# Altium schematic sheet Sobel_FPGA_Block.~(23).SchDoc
size A2
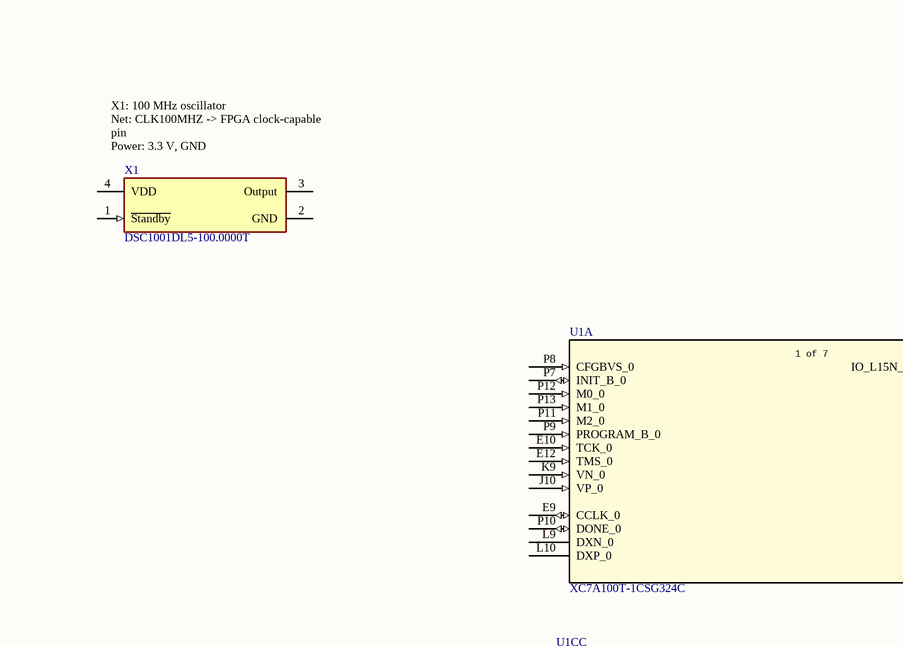
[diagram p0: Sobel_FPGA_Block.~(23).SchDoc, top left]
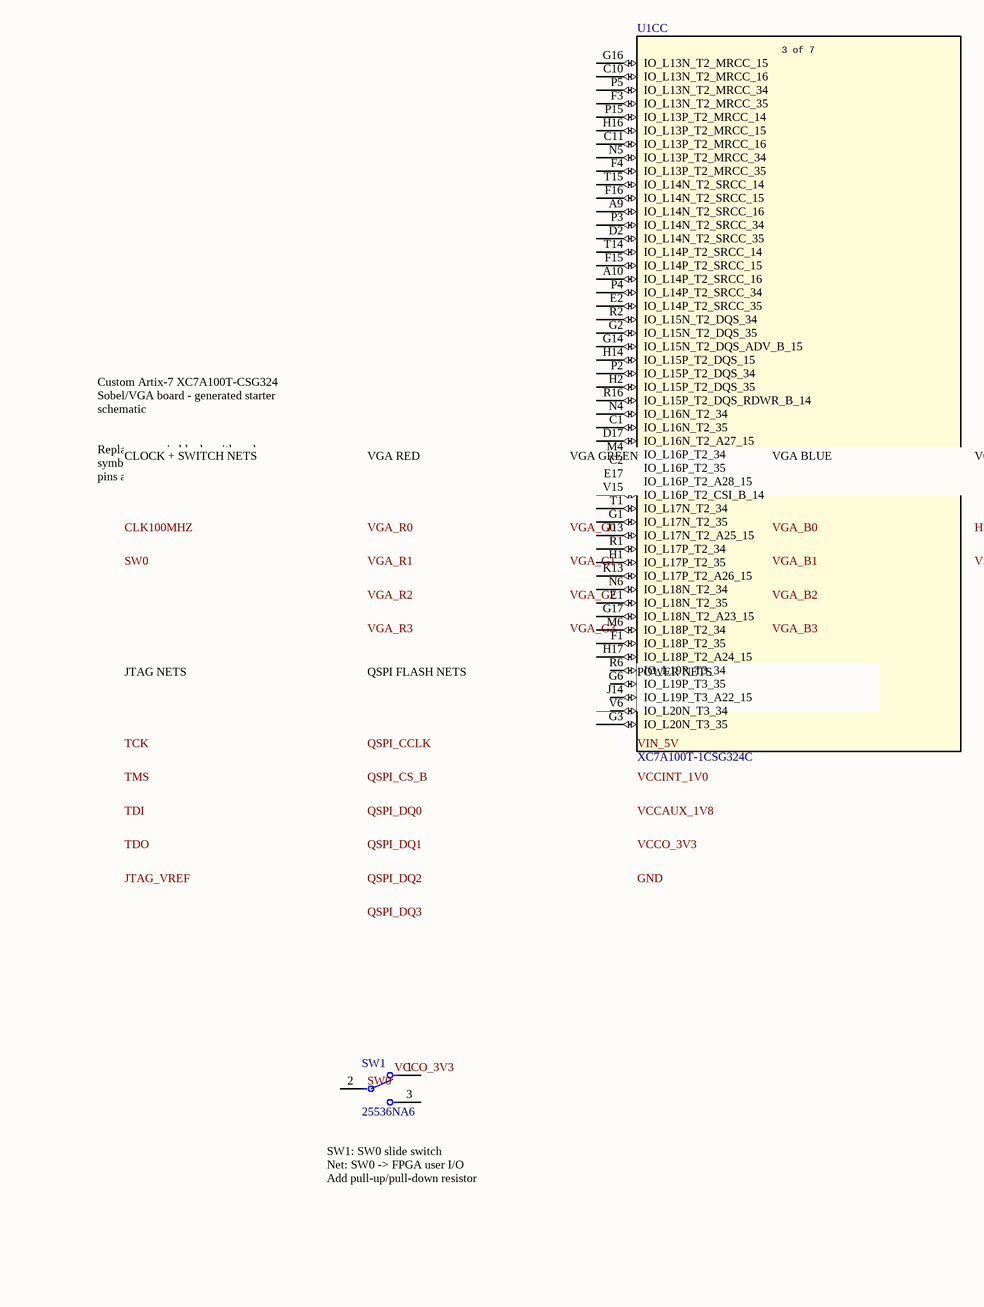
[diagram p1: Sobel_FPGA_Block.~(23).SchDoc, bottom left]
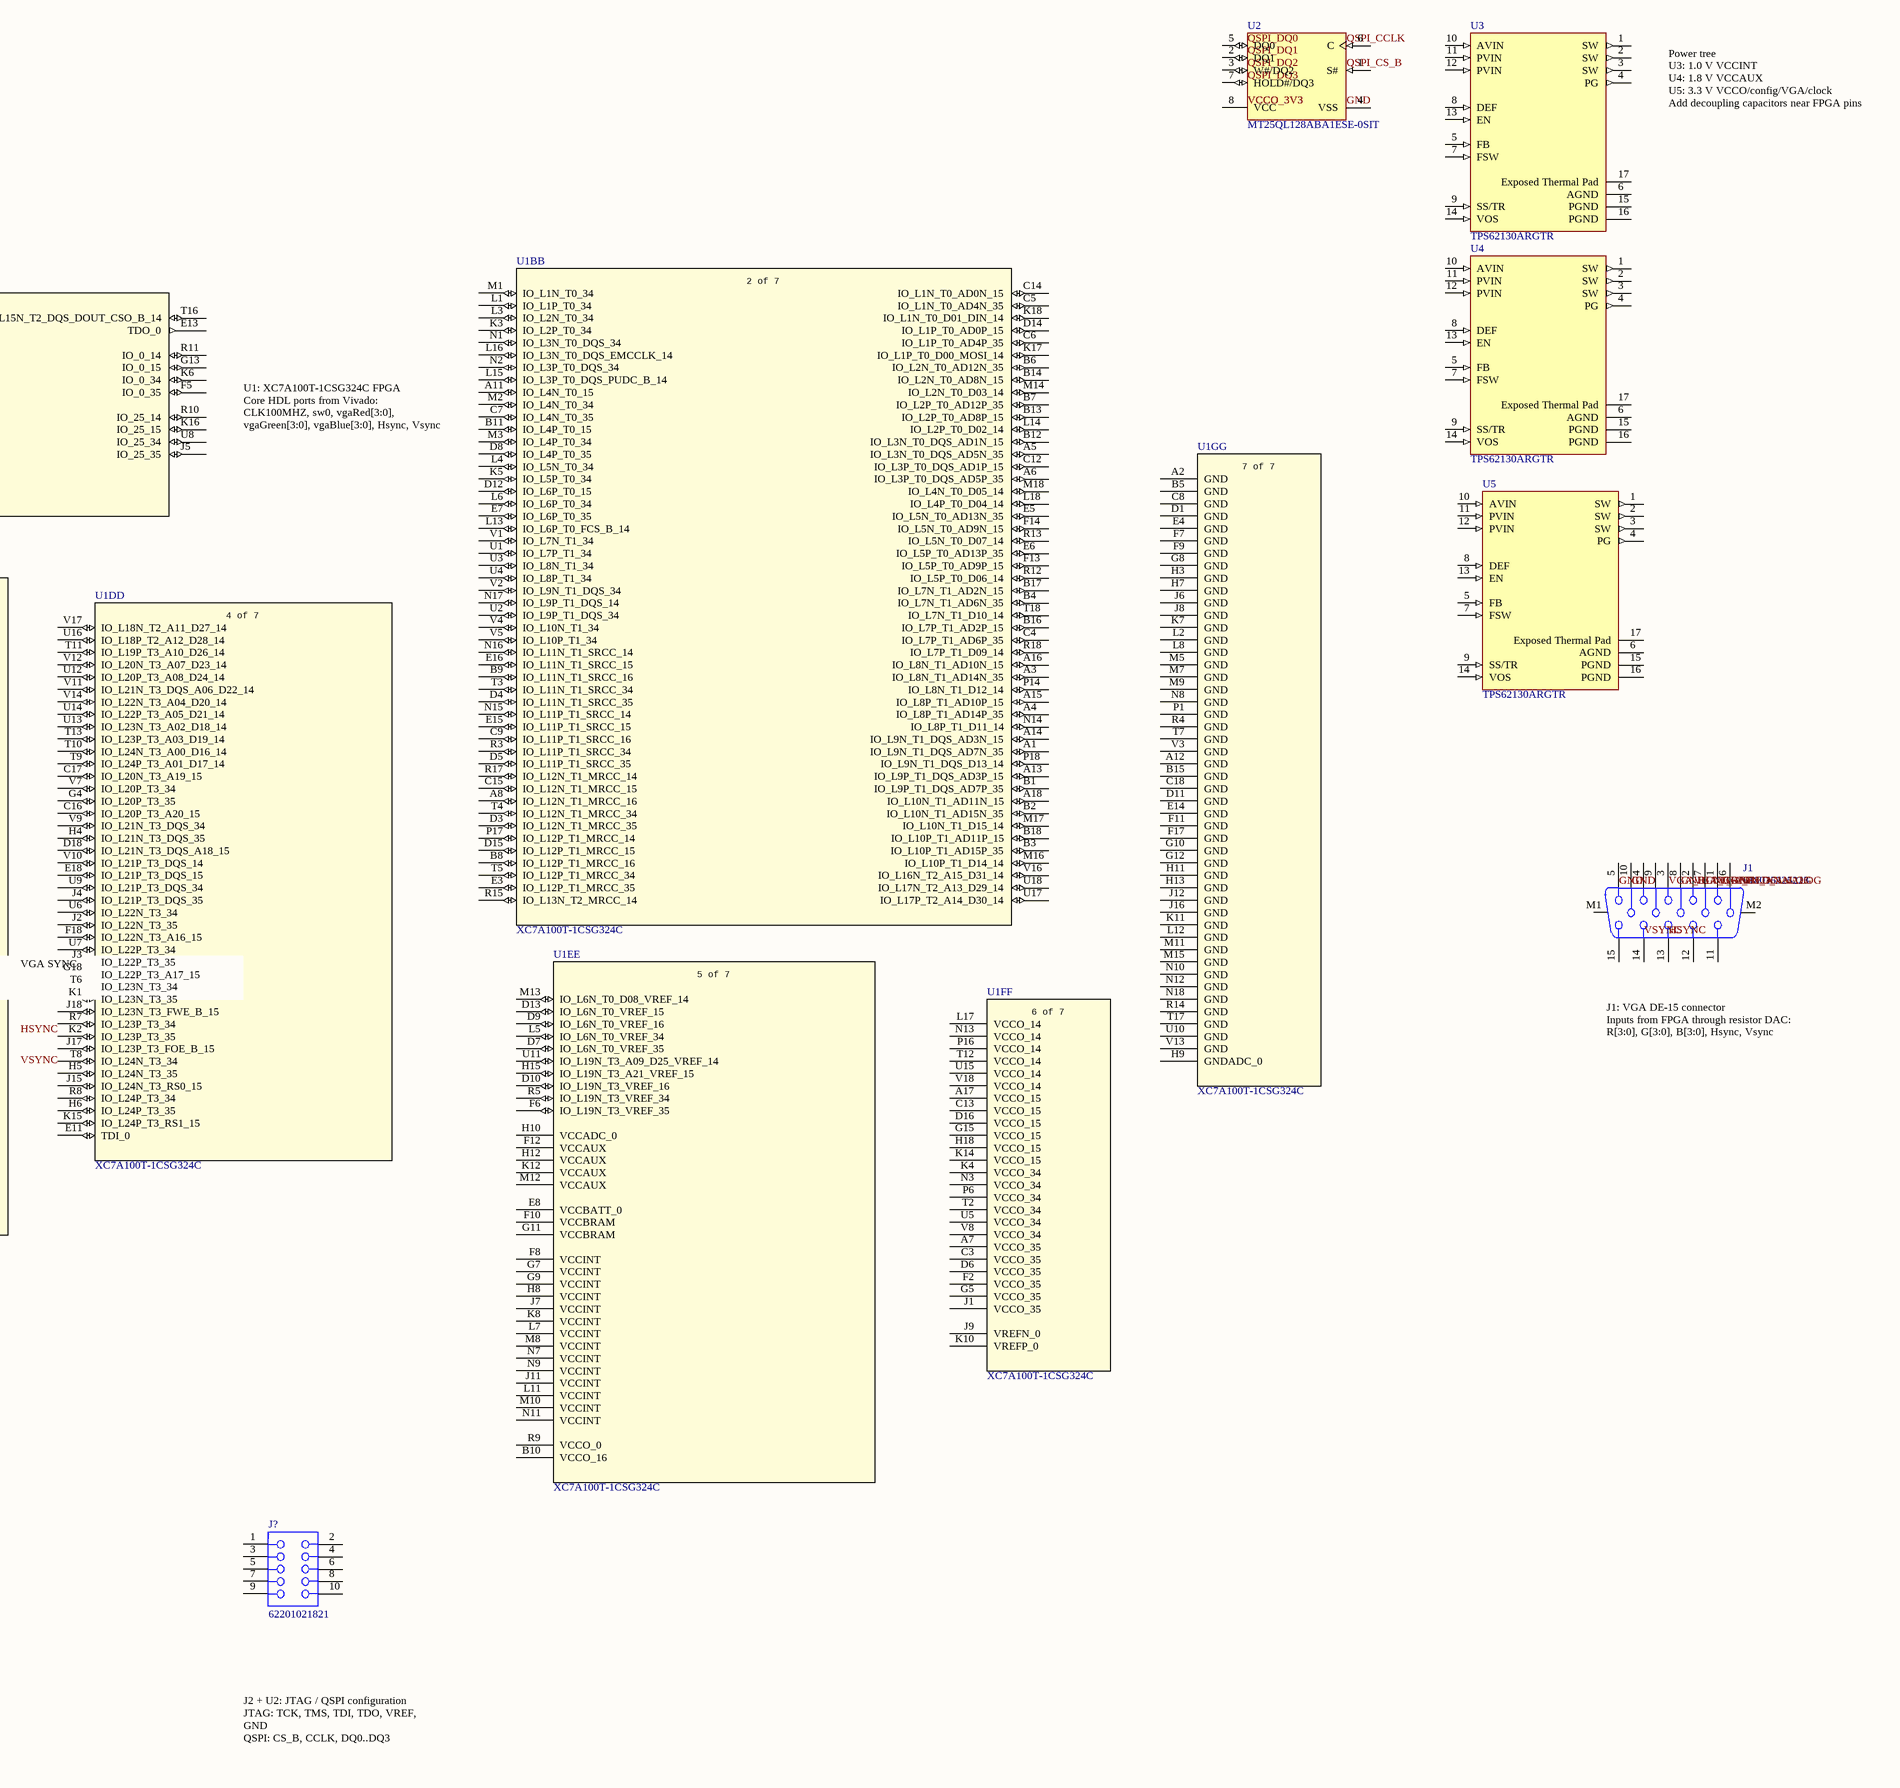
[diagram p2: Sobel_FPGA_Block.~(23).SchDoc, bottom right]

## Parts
J1  618015325223  [618015325223]
J?  62201021821  [62201021821]
SW1  25536NA6  [FP-25536NA6-0]
U1  XC7A100T-1CSG324C  [CSG324_XIL]  (part A of 7)
U1B  XC7A100T-1CSG324C  [CSG324_XIL]  (part B of 7)
U1C  XC7A100T-1CSG324C  [CSG324_XIL]  (part C of 7)
U1D  XC7A100T-1CSG324C  [CSG324_XIL]  (part D of 7)
U1E  XC7A100T-1CSG324C  [CSG324_XIL]  (part E of 7)
U1F  XC7A100T-1CSG324C  [CSG324_XIL]  (part F of 7)
U1G  XC7A100T-1CSG324C  [CSG324_XIL]  (part G of 7)
U2  MT25QL128ABA1ESE-0SIT  [MICT-SE-8_M]
U3  TPS62130ARGTR  [FP-RGT0016C-IPC_C]
U4  TPS62130ARGTR  [FP-RGT0016C-IPC_C]
U5  TPS62130ARGTR  [FP-RGT0016C-IPC_C]
X1  DSC1001DL5-100.0000T  [FP-CDFN2520-4LD-PL-1-MFG]

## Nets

Not connected (* = marked no-connect by the designer): J1 1 2 3 4 5 6 7 8 9 10 11 12 13 14 15 M1 M2; J? 1 2 3 4 5 6 7 8 9 10; SW1 1 2 3; U1 E9(CCLK_0) E10(TCK_0) E12(TMS_0) E13(TDO_0) F5(IO_0_35) G13(IO_0_15) J5(IO_25_35) J10(VP_0) K6(IO_0_34) K9(VN_0) K16(IO_25_15) L9(DXN_0) L10(DXP_0) P7(INIT_B_0) P8(CFGBVS_0) P9(PROGRAM_B_0) P10(DONE_0) P11(M2_0) P12(M0_0) P13(M1_0) R10(IO_25_14) R11(IO_0_14) T16(IO_L15N_T2_DQS_DOUT_CSO_B_14) U8(IO_25_34); U1B A1(IO_L9N_T1_DQS_AD7N_35) A3(IO_L8N_T1_AD14N_35) A4(IO_L8P_T1_AD14P_35) A5(IO_L3N_T0_DQS_AD5N_35) A6(IO_L3P_T0_DQS_AD5P_35) A8(IO_L12N_T1_MRCC_16) A11(IO_L4N_T0_15) A13(IO_L9P_T1_DQS_AD3P_15) A14(IO_L9N_T1_DQS_AD3N_15) A15(IO_L8P_T1_AD10P_15) A16(IO_L8N_T1_AD10N_15) A18(IO_L10N_T1_AD11N_15) B1(IO_L9P_T1_DQS_AD7P_35) B2(IO_L10N_T1_AD15N_35) B3(IO_L10P_T1_AD15P_35) B4(IO_L7N_T1_AD6N_35) B6(IO_L2N_T0_AD12N_35) B7(IO_L2P_T0_AD12P_35) B8(IO_L12P_T1_MRCC_16) B9(IO_L11N_T1_SRCC_16) B11(IO_L4P_T0_15) B12(IO_L3N_T0_DQS_AD1N_15) B13(IO_L2P_T0_AD8P_15) B14(IO_L2N_T0_AD8N_15) B16(IO_L7P_T1_AD2P_15) B17(IO_L7N_T1_AD2N_15) B18(IO_L10P_T1_AD11P_15) C4(IO_L7P_T1_AD6P_35) C5(IO_L1N_T0_AD4N_35) C6(IO_L1P_T0_AD4P_35) C7(IO_L4N_T0_35) C9(IO_L11P_T1_SRCC_16) C12(IO_L3P_T0_DQS_AD1P_15) C14(IO_L1N_T0_AD0N_15) C15(IO_L12N_T1_MRCC_15) D3(IO_L12N_T1_MRCC_35) D4(IO_L11N_T1_SRCC_35) D5(IO_L11P_T1_SRCC_35) D8(IO_L4P_T0_35) D12(IO_L6P_T0_15) D14(IO_L1P_T0_AD0P_15) D15(IO_L12P_T1_MRCC_15) E3(IO_L12P_T1_MRCC_35) E5(IO_L5N_T0_AD13N_35) E6(IO_L5P_T0_AD13P_35) E7(IO_L6P_T0_35) E15(IO_L11P_T1_SRCC_15) E16(IO_L11N_T1_SRCC_15) F13(IO_L5P_T0_AD9P_15) F14(IO_L5N_T0_AD9N_15) K3(IO_L2P_T0_34) K5(IO_L5P_T0_34) K17(IO_L1P_T0_D00_MOSI_14) K18(IO_L1N_T0_D01_DIN_14) L1(IO_L1P_T0_34) L3(IO_L2N_T0_34) L4(IO_L5N_T0_34) L6(IO_L6P_T0_34) L13(IO_L6P_T0_FCS_B_14) L14(IO_L2P_T0_D02_14) L15(IO_L3P_T0_DQS_PUDC_B_14) L16(IO_L3N_T0_DQS_EMCCLK_14) L18(IO_L4P_T0_D04_14) M1(IO_L1N_T0_34) M2(IO_L4N_T0_34) M3(IO_L4P_T0_34) M14(IO_L2N_T0_D03_14) M16(IO_L10P_T1_D14_14) M17(IO_L10N_T1_D15_14) M18(IO_L4N_T0_D05_14) N1(IO_L3N_T0_DQS_34) N2(IO_L3P_T0_DQS_34) N14(IO_L8P_T1_D11_14) N15(IO_L11P_T1_SRCC_14) N16(IO_L11N_T1_SRCC_14) N17(IO_L9P_T1_DQS_14) P14(IO_L8N_T1_D12_14) P17(IO_L12P_T1_MRCC_14) P18(IO_L9N_T1_DQS_D13_14) R3(IO_L11P_T1_SRCC_34) R12(IO_L5P_T0_D06_14) R13(IO_L5N_T0_D07_14) R15(IO_L13N_T2_MRCC_14) R17(IO_L12N_T1_MRCC_14) R18(IO_L7P_T1_D09_14) T3(IO_L11N_T1_SRCC_34) T4(IO_L12N_T1_MRCC_34) T5(IO_L12P_T1_MRCC_34) T18(IO_L7N_T1_D10_14) U1(IO_L7P_T1_34) U2(IO_L9P_T1_DQS_34) U3(IO_L8N_T1_34) U4(IO_L8P_T1_34) U17(IO_L17P_T2_A14_D30_14) U18(IO_L17N_T2_A13_D29_14) V1(IO_L7N_T1_34) V2(IO_L9N_T1_DQS_34) V4(IO_L10N_T1_34) V5(IO_L10P_T1_34) V16(IO_L16N_T2_A15_D31_14); U1C A9(IO_L14N_T2_SRCC_16) A10(IO_L14P_T2_SRCC_16) C1(IO_L16N_T2_35) C2(IO_L16P_T2_35) C10(IO_L13N_T2_MRCC_16) C11(IO_L13P_T2_MRCC_16) D2(IO_L14N_T2_SRCC_35) D17(IO_L16N_T2_A27_15) E1(IO_L18N_T2_35) E2(IO_L14P_T2_SRCC_35) E17(IO_L16P_T2_A28_15) F1(IO_L18P_T2_35) F3(IO_L13N_T2_MRCC_35) F4(IO_L13P_T2_MRCC_35) F15(IO_L14P_T2_SRCC_15) F16(IO_L14N_T2_SRCC_15) G1(IO_L17N_T2_35) G2(IO_L15N_T2_DQS_35) G3(IO_L20N_T3_35) G6(IO_L19P_T3_35) G14(IO_L15N_T2_DQS_ADV_B_15) G16(IO_L13N_T2_MRCC_15) G17(IO_L18N_T2_A23_15) H1(IO_L17P_T2_35) H2(IO_L15P_T2_DQS_35) H14(IO_L15P_T2_DQS_15) H16(IO_L13P_T2_MRCC_15) H17(IO_L18P_T2_A24_15) J13(IO_L17N_T2_A25_15) J14(IO_L19P_T3_A22_15) K13(IO_L17P_T2_A26_15) M4(IO_L16P_T2_34) M6(IO_L18P_T2_34) N4(IO_L16N_T2_34) N5(IO_L13P_T2_MRCC_34) N6(IO_L18N_T2_34) P2(IO_L15P_T2_DQS_34) P3(IO_L14N_T2_SRCC_34) P4(IO_L14P_T2_SRCC_34) P5(IO_L13N_T2_MRCC_34) P15(IO_L13P_T2_MRCC_14) R1(IO_L17P_T2_34) R2(IO_L15N_T2_DQS_34) R6(IO_L19P_T3_34) R16(IO_L15P_T2_DQS_RDWR_B_14) T1(IO_L17N_T2_34) T14(IO_L14P_T2_SRCC_14) T15(IO_L14N_T2_SRCC_14) V6(IO_L20N_T3_34) V15(IO_L16P_T2_CSI_B_14); U1D C16(IO_L20P_T3_A20_15) C17(IO_L20N_T3_A19_15) D18(IO_L21N_T3_DQS_A18_15) E11(TDI_0) E18(IO_L21P_T3_DQS_15) F18(IO_L22N_T3_A16_15) G4(IO_L20P_T3_35) G18(IO_L22P_T3_A17_15) H4(IO_L21N_T3_DQS_35) H5(IO_L24N_T3_35) H6(IO_L24P_T3_35) J2(IO_L22N_T3_35) J3(IO_L22P_T3_35) J4(IO_L21P_T3_DQS_35) J15(IO_L24N_T3_RS0_15) J17(IO_L23P_T3_FOE_B_15) J18(IO_L23N_T3_FWE_B_15) K1(IO_L23N_T3_35) K2(IO_L23P_T3_35) K15(IO_L24P_T3_RS1_15) R7(IO_L23P_T3_34) R8(IO_L24P_T3_34) T6(IO_L23N_T3_34) T8(IO_L24N_T3_34) T9(IO_L24P_T3_A01_D17_14) T10(IO_L24N_T3_A00_D16_14) T11(IO_L19P_T3_A10_D26_14) T13(IO_L23P_T3_A03_D19_14) U6(IO_L22N_T3_34) U7(IO_L22P_T3_34) U9(IO_L21P_T3_DQS_34) U12(IO_L20P_T3_A08_D24_14) U13(IO_L23N_T3_A02_D18_14) U14(IO_L22P_T3_A05_D21_14) U16(IO_L18P_T2_A12_D28_14) V7(IO_L20P_T3_34) V9(IO_L21N_T3_DQS_34) V10(IO_L21P_T3_DQS_14) V11(IO_L21N_T3_DQS_A06_D22_14) V12(IO_L20N_T3_A07_D23_14) V14(IO_L22N_T3_A04_D20_14) V17(IO_L18N_T2_A11_D27_14); U1E B10(VCCO_16) D7(IO_L6N_T0_VREF_35) D9(IO_L6N_T0_VREF_16) D10(IO_L19N_T3_VREF_16) D13(IO_L6N_T0_VREF_15) E8(VCCBATT_0) F6(IO_L19N_T3_VREF_35) F8(VCCINT) F10(VCCBRAM) F12(VCCAUX) G7(VCCINT) G9(VCCINT) G11(VCCBRAM) H8(VCCINT) H10(VCCADC_0) H12(VCCAUX) H15(IO_L19N_T3_A21_VREF_15) J7(VCCINT) J11(VCCINT) K8(VCCINT) K12(VCCAUX) L5(IO_L6N_T0_VREF_34) L7(VCCINT) L11(VCCINT) M8(VCCINT) M10(VCCINT) M12(VCCAUX) M13(IO_L6N_T0_D08_VREF_14) N7(VCCINT) N9(VCCINT) N11(VCCINT) R5(IO_L19N_T3_VREF_34) R9(VCCO_0) U11(IO_L19N_T3_A09_D25_VREF_14); U1F A7(VCCO_35) A17(VCCO_15) C3(VCCO_35) C13(VCCO_15) D6(VCCO_35) D16(VCCO_15) F2(VCCO_35) G5(VCCO_35) G15(VCCO_15) H18(VCCO_15) J1(VCCO_35) J9(VREFN_0) K4(VCCO_34) K10(VREFP_0) K14(VCCO_15) L17(VCCO_14) N3(VCCO_34) N13(VCCO_14) P6(VCCO_34) P16(VCCO_14) T2(VCCO_34) T12(VCCO_14) U5(VCCO_34) U15(VCCO_14) V8(VCCO_34) V18(VCCO_14); U1G A2(GND) A12(GND) B5(GND) B15(GND) C8(GND) C18(GND) D1(GND) D11(GND) E4(GND) E14(GND) F7(GND) F9(GND) F11(GND) F17(GND) G8(GND) G10(GND) G12(GND) H3(GND) H7(GND) H9(GNDADC_0) H11(GND) H13(GND) J6(GND) J8(GND) J12(GND) J16(GND) K7(GND) K11(GND) L2(GND) L8(GND) L12(GND) M5(GND) M7(GND) M9(GND) M11(GND) M15(GND) N8(GND) N10(GND) N12(GND) N18(GND) P1(GND) R4(GND) R14(GND) T7(GND) T17(GND) U10(GND) V3(GND) V13(GND); U2 1(S#) 2(DQ1) 3(W#/DQ2) 4(VSS) 5(DQ0) 6(C) 7(HOLD#/DQ3) 8(VCC); U3 1(SW) 2(SW) 3(SW) 4(PG) 5(FB) 6(AGND) 7(FSW) 8(DEF) 9(SS/TR) 10(AVIN) 11(PVIN) 12(PVIN) 13(EN) 14(VOS) 15(PGND) 16(PGND) 17(Exposed_Thermal_Pad); U4 1(SW) 2(SW) 3(SW) 4(PG) 5(FB) 6(AGND) 7(FSW) 8(DEF) 9(SS/TR) 10(AVIN) 11(PVIN) 12(PVIN) 13(EN) 14(VOS) 15(PGND) 16(PGND) 17(Exposed_Thermal_Pad); U5 1(SW) 2(SW) 3(SW) 4(PG) 5(FB) 6(AGND) 7(FSW) 8(DEF) 9(SS/TR) 10(AVIN) 11(PVIN) 12(PVIN) 13(EN) 14(VOS) 15(PGND) 16(PGND) 17(Exposed_Thermal_Pad); X1 1(~{Standby}) 2(GND) 3(Output) 4(VDD)

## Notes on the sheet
- Power tree
  U3: 1.0 V VCCINT
  U4: 1.8 V VCCAUX
  U5: 3.3 V VCCO/config/VGA/clock
  Add decoupling capacitors near FPGA pins
- (near X1) X1: 100 MHz oscillator
  Net: CLK100MHZ -> FPGA clock-capable pin
  Power: 3.3 V, GND
- U1: XC7A100T-1CSG324C FPGA
  Core HDL ports from Vivado:
  CLK100MHZ, sw0, vgaRed[3:0], vgaGreen[3:0], vgaBlue[3:0], Hsync, Vsync
- Custom Artix-7 XC7A100T-CSG324 Sobel/VGA board - generated starter schematic
- Replace generic blocks with real symbols/parts, then assign final FPGA ball pins and run ERC.
- CLOCK + SWITCH NETS
- (near U1C) VGA RED
- (near U1C) VGA GREEN
- (near U1D) VGA BLUE
- (near U1D) VGA SYNC
- J1: VGA DE-15 connector
  Inputs from FPGA through resistor DAC:
  R[3:0], G[3:0], B[3:0], Hsync, Vsync
- JTAG NETS
- (near U1C) QSPI FLASH NETS
- (near U1C) POWER NETS
- (near SW1) SW1: SW0 slide switch
  Net: SW0 -> FPGA user I/O
  Add pull-up/pull-down resistor
- J2 + U2: JTAG / QSPI configuration
  JTAG: TCK, TMS, TDI, TDO, VREF, GND
  QSPI: CS_B, CCLK, DQ0..DQ3
- Labels drawn without touching a wire or pin: CLK100MHZ, GND, HSYNC, JTAG_VREF, QSPI_CCLK, QSPI_CS_B, QSPI_DQ0, QSPI_DQ1, QSPI_DQ2, QSPI_DQ3, SW0, TCK, TDI, TDO, TMS, VCCAUX_1V8, VCCINT_1V0, VCCO_3V3, VGA_B0, VGA_B1, VGA_B2, VGA_B3, VGA_BLUE_ANALOG, VGA_G0, VGA_G1, VGA_G2, VGA_G3, VGA_GREEN_ANALOG, VGA_R0, VGA_R1, VGA_R2, VGA_R3, VGA_RED_ANALOG, VIN_5V, VSYNC

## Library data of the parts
J1 = CMP-002-00072-1: D-sub, Female High Density Angled Pcb Connector Without Hex Screw, 15 Pins
J? = CMP-002-00073-1: Connector Header Surface Mount 10 position 0.050" (1.27mm)-JTAG Connector; Gender: Female
SW1 = CMP-011-00013-1: Switch Slide ON ON SPDT Side Slide 1A 30VDC 20000Cycles PC Pins Thru-Hole; Max Current Rating: 3A
U1 U1B U1C U1D U1E U1F U1G = XC7A100T-1CSG324C: Description; Manufacturer_Name: Xilinx Inc
U2 = CMP-019-00049-1: 3.6 V 35 mA 128 Mbit 133 MHz Surface Mount FLASH - NOR Memory IC - SOIC-16; Min Supply Voltage: 2.7V; Memory Size: 16MB; Clock Frequency: 133MHz; Max Supply Voltage: 3.6V
U3-U5 = CMP-019-00050-1: 3-V to 17-V, 3-A step-down converter with DCS-control in 3x3 QFN package 16-VQFN -40 to 125; Output Current: 3A; Output Voltage: 6V; Nominal Supply Current: 17µA; Min Supply Voltage: 3V; Max Supply Voltage: 17V
X1 = CMP-00023-00003-1: 3.3 V 100 MHz Surface Mount Low-Power Precision CMOS Oscillator - VDFN-4; Frequency: 100MHz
